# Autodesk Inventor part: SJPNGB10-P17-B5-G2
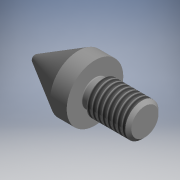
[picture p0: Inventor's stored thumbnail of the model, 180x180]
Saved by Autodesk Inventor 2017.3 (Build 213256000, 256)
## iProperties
Part Number: SJPNGB10-P17-B5-G2
Material: Generic
Catalog Web Link: www.cadenas.de
Description: JPNG, GJPNG, BJPNG, SJPNG-Screw - In Locating Pins - Full Threaded
Vendor: MISUMI
Document SubType Name: Modeling
Designer: partserver
Manufacturer: MISUMI
Mass: 3.33309 g
Surface Area: 14.3981 cm^2
Volume: 3.33309 cm^3
Density: 1 g/cm^3
Appearance: PSOLRGB-175-175-175
Category: PARTsolutions
Company: MISUMI
Title: SJPNGB10-P17-B5-G2
Author: Cadenas PARTsolutions
Comments: Screw - In Locating Pins - Full Threaded
PSOL_IDENT_0: {$CADENAS_DATA\23d-libs\misumi\metric\14_locating_pins\jpng.prj},250 {VTYP=3D},{NB=SJPNGB10-P17-B5-G
PSOL_IDENT_1: 2},{LINA=SJPNGB10-P17-B5-G2},{NN=JPNG, GJPNG, BJPNG, SJPNG},{DATE=19.01.2022 02:35:35},{GEOMDATE=13.
PSOL_IDENT_2: 01.2022 04:25:00},{VERSION=},{LINEID=70},{WBVAR=MAT,ST,HARD,TSS,P,B,R,G,ALT1,SC,ALT2,ALT3,S},{WBNUME
PSOL_IDENT_3: RIC=P,B,R,G,SC,S}  {NB=SJPNGB10-P17-B5-G2},{LINA=SJPNGB10-P17-B5-G2},{KT=DUMMY},{PN=SJPNGB10-P17-B5-
PSOL_IDENT_4: G2},{TYPE=SJPNG},{MAT=SUS304},{MATALG= 'SKS3','SKS3 Equivalent' , 'SUS304','SUS304' },{ST=-},{STALG=
PSOL_IDENT_5: '-','-' },{HARD=-},{HARDALG= '-','-' },{TSS=B},{TSSALG= 'A' , 'B' , 'C' },{M=10},{P=17.0},{PALG=[11
PSOL_IDENT_6: .0:17.0/0.1]},{B=5.0},{BALG=[3.0:30.0/0.1]},{R=0},{RALG=[0]},{RAMIN=9},{RAMAX=500},{RCMIN=1},{RCMAX=
PSOL_IDENT_7: 8},{RPN=},{G=2},{GALG=[1:17/1]},{GMIN=1},{GMAX=17},{GPN=-G2},{X=17},{ALT1=},{ALT1ALG= '','w/o SC (Wr
PSOL_IDENT_8: ench Flats)' , 'SC','with SC (Wrench Flats)' },{SC=0},{SCALG=[0]},{SCMIN=14},{SCMAX=16},{ALT1L3D=20}
PSOL_IDENT_9: ,{ALT1PN=},{ALT2=},{ALT2ALG= '','Not applicable' },{ALT2PN=},{ALT3=},{ALT3ALG= '','Not applicable' }
PSOL_IDENT_10: ,{ALT3PN=},{S=0},{SALG=[0]},{SMAX=0},{E=0.0},{LL1=nan},{LL2=12.990381},{LL3=14.722432},{LL3D=12.9903
PSOL_IDENT_11: 81},{AA=2.5},{BB=7.7},{E1=2.3},{PITCH=1.5}
NB: SJPNGB10-P17-B5-G2
NN: JPNG, GJPNG, BJPNG, SJPNG
NT: Screw - In Locating Pins - Full Threaded
NBSYN: $PN.
LINA: SJPNGB10-P17-B5-G2
CATALOG: Misumi
PN: SJPNGB10-P17-B5-G2
MAT: SUS304
ST: -
HARD: -
TSS: B
M: 10
P: 17
B: 5
R: 0
G: 2
ALT1: w/o SC (Wrench Flats)
SC: 0
ALT2: Not applicable
ALT3: Not applicable
S: 0
E: 0
AA: 2.5
BB: 7.7
SUPPLIER: MISUMI
ARTICLENO: SJPNGB10-P17-B5-G2
BOMINFO: SJPNGB10-P17-B5-G2
CREATOR: CADENAS GmbH
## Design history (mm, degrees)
sketch "Sketch_2"
  geometry: L1 (17.99, 0)-(0, 0); L2 (0, 0)-(0, 8.5); L3 (0, 8.5)-(5, 8.5); L4 (5, 8.5)-(17.99, 1); L5 (17.99, 1)-(17.99, 0); L6 (17.99, 0)-(0, 0)
  constraints: 12 end point
revolve "Revolution1" sketch "Sketch_2" stored, may be unused: angle "d0" = 360 deg
sketch "Sketch_6"
  geometry: L1 (0, 0)-(-15, 0); L2 (-15, 0)-(-15, 4.08); L3 (-15, 4.08)-(-14.08, 5); L4 (-14.08, 5)-(-2.5, 5); L5 (-2.5, 5)-(-2.5, 4.05); L6 (-2.3, 3.85)-(-0.2, 3.85); L7 (0, 4.05)-(0, 0); L8 (0, 0)-(-15, 0); A1 r 0.2 centre (-2.3, 4.05) between (-2.5, 4.05) and (-2.3, 3.85); A2 r 0.2 centre (-0.2, 4.05) between (-0.2, 3.85) and (0, 4.05)
  constraints: 16 end point, 4 point on circle, 2 centre point
revolve "Revolution2" sketch "Sketch_6" stored, may be unused: angle "d1" = 360 deg
thread "Thread1" dims "d2" = 11.58, "d3" = 0
node "to_base_XY"
node "to_base_YZ"
node "to_base_ZX"
node "to_base_X"
node "to_base_Y"
node "to_base_Z"
node "to_base_Center"
body "Solid1"
other parameters: "d4" = 0
